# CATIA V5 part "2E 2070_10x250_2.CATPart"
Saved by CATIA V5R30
Part number: 2E 2070_10x250_2
Definition: E 2070_10x250_1
Nomenclature: E 2070_10x250_1
Source: Unknown
Description: PART--DESC
Bounding box of the stored display mesh (mm): x 201.25 to 251.75, y -4.99 to 4.99, z 39.5 to 49.5
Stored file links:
  E:\Bakalarka\Model\Forma_v7\2E 2070_10x250_2.CATPart
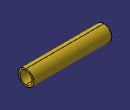
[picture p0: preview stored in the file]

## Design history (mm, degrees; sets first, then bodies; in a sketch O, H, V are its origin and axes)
Body1 "MANIFOLD_SOLID_BREP #156" (main body)
  Solid1: solid without history
  Pocket1: profile face of Solid1, direction along face of Solid1 reversed, length 199.5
